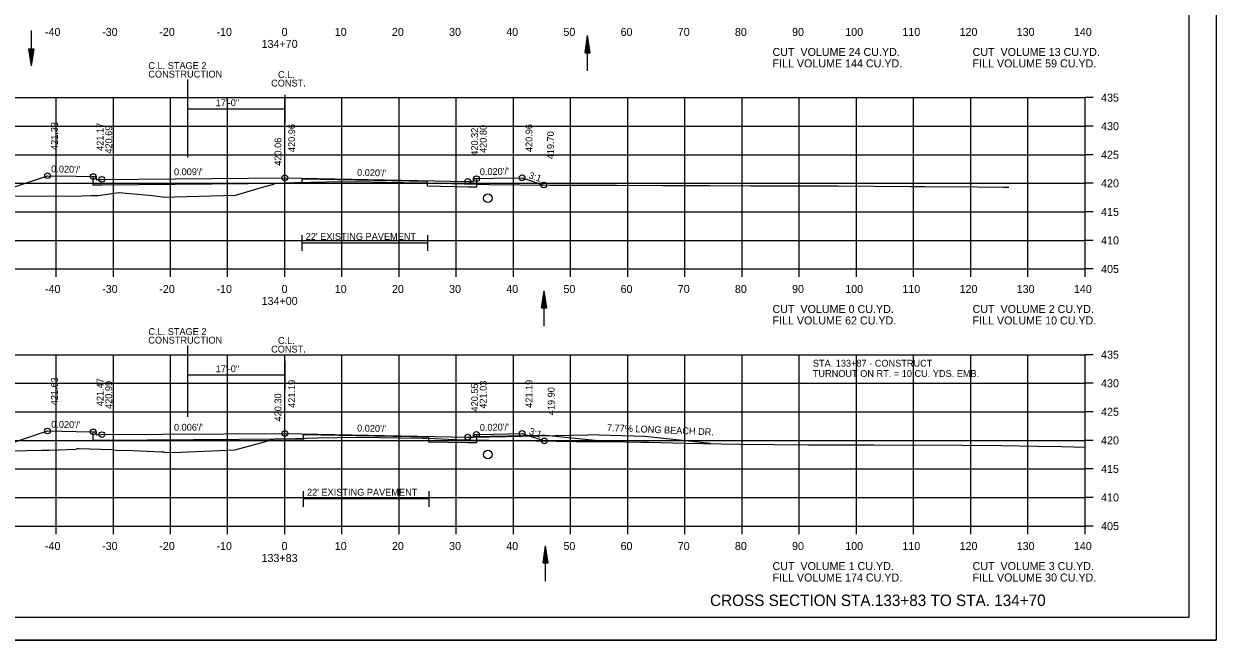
# Model space of a CAD drawing. Extents: x 1538688 to 1540766, y 656250 to 671912.
# Drawn here: x 1538812.5 to 1539021.1, y 661244.7 to 661352.6 of the extents above; entities that cross this region are included whole.
import ezdxf

# ---------------------------------------------------------------- set-up
doc = ezdxf.new("R2010")
doc.units = 0
for name, color, linetype in [('15', 7, 'Continuous'), ('16', 7, 'Continuous'), ('18', 7, 'Continuous'), ('20', 7, 'Continuous'), ('22', 7, 'Continuous'), ('26', 7, 'Continuous'), ('39', 7, 'Continuous'), ('41', 7, 'Continuous'), ('42', 7, 'Continuous'), ('7', 7, 'Continuous'), ('Borings', 7, 'Continuous'), ('Default', 7, 'Continuous'), ('Horizontal Alignment', 7, 'Continuous'), ('RipRap', 7, 'Continuous'), ('Wall Heights', 7, 'Continuous')]:
    doc.layers.add(name, color=color, linetype=linetype)

msp = doc.modelspace()

# ---------------------------------------------------------------- linework, layer by layer
at = {"layer": '15'}
for p, q in [((1538910.71, 661347.5), (1538911.16, 661350.5)), ((1538910.79, 661347.5), (1538911.16, 661349.99)), ((1538910.86, 661347.5), (1538911.16, 661349.48)), ((1538911.61, 661347.5), (1538911.16, 661350.5)), ((1538911.54, 661347.5), (1538911.16, 661349.99)), ((1538911.46, 661347.5), (1538911.16, 661349.48)), ((1538813.36, 661348.2), (1538813.81, 661345.2)), ((1538813.36, 661348.2), (1538814.26, 661348.2)), ((1538813.44, 661348.2), (1538813.81, 661345.7)), ((1538813.51, 661348.2), (1538813.81, 661346.22)), ((1538813.59, 661348.2), (1538813.81, 661346.72)), ((1538813.66, 661348.2), (1538813.81, 661347.23)), ((1538813.74, 661348.2), (1538813.81, 661347.73)), ((1538814.26, 661348.2), (1538813.81, 661345.2)), ((1538813.96, 661348.2), (1538813.81, 661347.23)), ((1538814.11, 661348.2), (1538813.81, 661346.22)), ((1538814.19, 661348.2), (1538813.81, 661345.7)), ((1538814.03, 661348.2), (1538813.81, 661346.72)), ((1538813.88, 661348.2), (1538813.81, 661347.73)), ((1538910.71, 661347.5), (1538911.61, 661347.5)), ((1538910.94, 661347.5), (1538911.16, 661348.98)), ((1538911.01, 661347.5), (1538911.16, 661348.47)), ((1538911.09, 661347.5), (1538911.16, 661347.97)), ((1538911.38, 661347.5), (1538911.16, 661348.98)), ((1538911.31, 661347.5), (1538911.16, 661348.47)), ((1538911.23, 661347.5), (1538911.16, 661347.97)), ((1538903.09, 661302.85), (1538903.54, 661305.85)), ((1538903.99, 661302.85), (1538903.54, 661305.85)), ((1538903.17, 661302.85), (1538903.54, 661305.34)), ((1538903.24, 661302.85), (1538903.54, 661304.83)), ((1538903.32, 661302.85), (1538903.54, 661304.33)), ((1538903.4, 661302.85), (1538903.54, 661303.82)), ((1538903.92, 661302.85), (1538903.54, 661305.34)), ((1538903.84, 661302.85), (1538903.54, 661304.83)), ((1538903.77, 661302.85), (1538903.54, 661304.33)), ((1538903.69, 661302.85), (1538903.54, 661303.82)), ((1538903.09, 661302.85), (1538903.99, 661302.85)), ((1538903.47, 661302.85), (1538903.54, 661303.32)), ((1538903.61, 661302.85), (1538903.54, 661303.32)), ((1538903.36, 661258.19), (1538903.81, 661261.19)), ((1538903.44, 661258.19), (1538903.81, 661260.69)), ((1538903.51, 661258.19), (1538903.81, 661260.18)), ((1538903.59, 661258.19), (1538903.81, 661259.68)), ((1538904.26, 661258.19), (1538903.81, 661261.19)), ((1538904.19, 661258.19), (1538903.81, 661260.69)), ((1538904.11, 661258.19), (1538903.81, 661260.18)), ((1538904.03, 661258.19), (1538903.81, 661259.68)), ((1538903.36, 661258.19), (1538904.26, 661258.19)), ((1538903.67, 661258.19), (1538903.81, 661259.17)), ((1538903.74, 661258.19), (1538903.81, 661258.67)), ((1538903.96, 661258.19), (1538903.81, 661259.17)), ((1538903.88, 661258.19), (1538903.81, 661258.67))]:
    msp.add_line(p, q, dxfattribs=at)
at = {"layer": '16'}
for p, q in [((1538891.18, 661280.19), (1538911.17, 661280.59)), ((1538891.18, 661280.3), (1538903.18, 661280.54)), ((1538914.15, 661279.44), (1538903.18, 661280.54)), ((1538921.17, 661280.33), (1538911.17, 661280.59)), ((1538932.64, 661279.09), (1538921.17, 661280.33))]:
    msp.add_line(p, q, dxfattribs=at)
at = {"layer": '18'}
for points in [[(1538809.48, 661322.39), (1538822.68, 661322.43), (1538824.23, 661322.5), (1538824.62, 661322.5), (1538824.96, 661322.52), (1538825.5, 661322.5), (1538829.15, 661323.05), (1538834.99, 661322.5), (1538837.19, 661322.23), (1538838.95, 661322.26), (1538849.56, 661322.59), (1538854.69, 661324.1), (1538856.25, 661324.5), (1538856.32, 661324.53), (1538856.53, 661324.68), (1538858.29, 661324.72), (1538859.86, 661324.76), (1538865.42, 661324.88), (1538870.63, 661324.98), (1538875.93, 661324.86), (1538882.01, 661324.75), (1538882.96, 661324.74), (1538893.99, 661324.43), (1538904.52, 661324.35), (1538916.23, 661324.31), (1538924.16, 661324.25), (1538932.48, 661324.26), (1538939.67, 661324.22), (1538946.19, 661324.23), (1538954.91, 661324.18), (1538967.64, 661324.1), (1538970.06, 661324.08), (1538979.33, 661324.02), (1538983.91, 661323.98), (1538984.85, 661323.99)], [(1538807.8, 661277.78), (1538815.66, 661277.95), (1538815.73, 661277.95), (1538816.96, 661277.95), (1538821.68, 661278.11), (1538821.9, 661278.2), (1538822.13, 661278.22), (1538827.92, 661278.03), (1538829.02, 661277.88), (1538830.36, 661277.92), (1538836.61, 661277.64), (1538836.95, 661277.63), (1538837.29, 661277.5), (1538839.97, 661277.59), (1538849.46, 661277.98), (1538854.2, 661279.25), (1538856.41, 661279.89), (1538857.66, 661279.94), (1538860.03, 661280), (1538863.9, 661280.08), (1538870.75, 661280.23), (1538870.84, 661280.21), (1538874.86, 661280.14), (1538882.22, 661280.03), (1538883.28, 661280.02), (1538889.11, 661279.76), (1538889.79, 661279.74), (1538902.07, 661279.58), (1538909.16, 661279.45), (1538915.03, 661279.44), (1538920.47, 661279.34), (1538921.91, 661279.31), (1538928.16, 661279.17), (1538937.79, 661278.99), (1538949.82, 661278.87), (1538958.4, 661278.87), (1538961.21, 661278.84), (1538976.59, 661278.81), (1538983.55, 661278.75), (1538989.87, 661278.65), (1538994.09, 661278.55), (1538998.18, 661278.43)]]:
    msp.add_lwpolyline(points, dxfattribs=at)
at = {"layer": '20'}
for points in [[(1538805.94, 661322.4), (1538816.67, 661325.98), (1538821.67, 661325.88), (1538824.67, 661325.82), (1538825.17, 661325.82), (1538825.18, 661325.32), (1538826.18, 661325.34), (1538858.18, 661325.62), (1538890.18, 661324.98), (1538891.18, 661324.96), (1538891.19, 661325.46), (1538891.69, 661325.46), (1538894.69, 661325.52), (1538899.69, 661325.62), (1538903.47, 661324.35)], [(1538803.72, 661277.74), (1538804.88, 661277.36), (1538816.67, 661281.29), (1538821.67, 661281.19), (1538824.67, 661281.13), (1538825.17, 661281.13), (1538825.18, 661280.63), (1538826.18, 661280.65), (1538858.18, 661280.85), (1538890.18, 661280.21), (1538891.18, 661280.19), (1538891.19, 661280.69), (1538891.69, 661280.69), (1538894.69, 661280.75), (1538899.69, 661280.85), (1538903.58, 661279.55)]]:
    msp.add_lwpolyline(points, dxfattribs=at)
at = {"layer": '22'}
for p, q in [((1538718.18, 661339.65), (1538998.18, 661339.65)), ((1538818.18, 661309.65), (1538818.18, 661339.65)), ((1538828.18, 661309.65), (1538828.18, 661339.65)), ((1538838.18, 661309.65), (1538838.18, 661339.65)), ((1538848.18, 661309.65), (1538848.18, 661339.65)), ((1538858.18, 661309.65), (1538858.18, 661339.65)), ((1538868.18, 661309.65), (1538868.18, 661339.65)), ((1538878.18, 661309.65), (1538878.18, 661339.65)), ((1538888.18, 661309.65), (1538888.18, 661339.65)), ((1538898.18, 661309.65), (1538898.18, 661339.65)), ((1538908.18, 661309.65), (1538908.18, 661339.65)), ((1538918.18, 661309.65), (1538918.18, 661339.65)), ((1538928.18, 661309.65), (1538928.18, 661339.65)), ((1538938.18, 661309.65), (1538938.18, 661339.65)), ((1538948.18, 661309.65), (1538948.18, 661339.65)), ((1538958.18, 661309.65), (1538958.18, 661339.65)), ((1538968.18, 661309.65), (1538968.18, 661339.65)), ((1538978.18, 661309.65), (1538978.18, 661339.65)), ((1538988.18, 661309.65), (1538988.18, 661339.65)), ((1538998.18, 661309.65), (1538998.18, 661339.65)), ((1538718.18, 661334.65), (1538998.18, 661334.65)), ((1538718.18, 661329.65), (1538998.18, 661329.65)), ((1538718.18, 661324.65), (1538998.18, 661324.65)), ((1538718.18, 661319.65), (1538998.18, 661319.65)), ((1538718.18, 661314.65), (1538998.18, 661314.65)), ((1538718.18, 661309.65), (1538998.18, 661309.65)), ((1538718.18, 661294.65), (1538998.18, 661294.65)), ((1538818.18, 661264.65), (1538818.18, 661294.65)), ((1538828.18, 661264.65), (1538828.18, 661294.65)), ((1538838.18, 661264.65), (1538838.18, 661294.65)), ((1538848.18, 661264.65), (1538848.18, 661294.65)), ((1538858.18, 661264.65), (1538858.18, 661294.65)), ((1538868.18, 661264.65), (1538868.18, 661294.65)), ((1538878.18, 661264.65), (1538878.18, 661294.65)), ((1538888.18, 661264.65), (1538888.18, 661294.65)), ((1538898.18, 661264.65), (1538898.18, 661294.65)), ((1538908.18, 661264.65), (1538908.18, 661294.65)), ((1538918.18, 661264.65), (1538918.18, 661294.65)), ((1538928.18, 661264.65), (1538928.18, 661294.65)), ((1538938.18, 661264.65), (1538938.18, 661294.65)), ((1538948.18, 661264.65), (1538948.18, 661294.65)), ((1538958.18, 661264.65), (1538958.18, 661294.65)), ((1538968.18, 661264.65), (1538968.18, 661294.65)), ((1538978.18, 661264.65), (1538978.18, 661294.65)), ((1538988.18, 661264.65), (1538988.18, 661294.65)), ((1538998.18, 661264.65), (1538998.18, 661294.65)), ((1538718.18, 661289.65), (1538998.18, 661289.65)), ((1538718.18, 661284.65), (1538998.18, 661284.65)), ((1538718.18, 661279.65), (1538998.18, 661279.65)), ((1538718.18, 661274.65), (1538998.18, 661274.65)), ((1538718.18, 661269.65), (1538998.18, 661269.65)), ((1538718.18, 661264.65), (1538998.18, 661264.65))]:
    msp.add_line(p, q, dxfattribs=at)
at = {"layer": '26'}
msp.add_line((1538687.78, 661244.68), (1539021.11, 661244.68), dxfattribs=at)
msp.add_lwpolyline([(1538687.77, 661458.01), (1539021.11, 661458.01), (1539021.11, 661244.67), (1538687.77, 661244.67)], close=True, dxfattribs=at)
for centre in [(1538816.67, 661325.98), (1538824.67, 661325.82), (1538826.18, 661325.34), (1538858.18, 661325.62), (1538890.18, 661324.98), (1538891.69, 661325.46), (1538899.69, 661325.62), (1538903.47, 661324.35), (1538816.67, 661281.29), (1538824.67, 661281.13), (1538826.18, 661280.65), (1538858.18, 661280.85), (1538890.18, 661280.21), (1538891.69, 661280.69), (1538899.69, 661280.85), (1538903.58, 661279.55)]:
    msp.add_circle(centre, 0.5, dxfattribs=at)
at = {"layer": '39'}
for p, q in [((1538813.81, 661351.39), (1538813.81, 661345.2)), ((1538911.16, 661344.31), (1538911.16, 661350.5)), ((1538903.54, 661299.66), (1538903.54, 661305.85)), ((1538903.81, 661255.01), (1538903.81, 661261.19))]:
    msp.add_line(p, q, dxfattribs=at)
for centre in [(1538893.68, 661322.03), (1538893.68, 661277.18)]:
    msp.add_circle(centre, 0.75, dxfattribs=at)
at = {"layer": '7'}
for p, q in [((1538861.13, 661315.56), (1538861.13, 661312.81)), ((1538883.13, 661314.18), (1538861.13, 661314.18)), ((1538883.13, 661315.56), (1538883.13, 661312.81)), ((1538861.36, 661270.78), (1538861.36, 661268.04)), ((1538883.36, 661270.78), (1538883.36, 661268.04)), ((1538883.36, 661269.41), (1538861.36, 661269.41))]:
    msp.add_line(p, q, dxfattribs=at)
at = {"layer": 'Borings'}
for p, q in [((1538998.18, 661309.65), (1538998.18, 661339.65)), ((1538999.58, 661339.65), (1538998.18, 661339.65)), ((1538999.58, 661334.65), (1538998.18, 661334.65)), ((1538999.58, 661329.65), (1538998.18, 661329.65)), ((1538999.58, 661324.65), (1538998.18, 661324.65)), ((1538999.58, 661319.65), (1538998.18, 661319.65)), ((1538999.58, 661314.65), (1538998.18, 661314.65)), ((1538718.18, 661309.65), (1538998.18, 661309.65)), ((1538818.18, 661308.25), (1538818.18, 661309.65)), ((1538828.18, 661308.25), (1538828.18, 661309.65)), ((1538838.18, 661308.25), (1538838.18, 661309.65)), ((1538848.18, 661308.25), (1538848.18, 661309.65)), ((1538858.18, 661308.25), (1538858.18, 661309.65)), ((1538868.18, 661308.25), (1538868.18, 661309.65)), ((1538878.18, 661308.25), (1538878.18, 661309.65)), ((1538888.18, 661308.25), (1538888.18, 661309.65)), ((1538898.18, 661308.25), (1538898.18, 661309.65)), ((1538908.18, 661308.25), (1538908.18, 661309.65)), ((1538918.18, 661308.25), (1538918.18, 661309.65)), ((1538928.18, 661308.25), (1538928.18, 661309.65)), ((1538938.18, 661308.25), (1538938.18, 661309.65)), ((1538948.18, 661308.25), (1538948.18, 661309.65)), ((1538958.18, 661308.25), (1538958.18, 661309.65)), ((1538968.18, 661308.25), (1538968.18, 661309.65)), ((1538978.18, 661308.25), (1538978.18, 661309.65)), ((1538988.18, 661308.25), (1538988.18, 661309.65)), ((1538998.18, 661308.25), (1538998.18, 661309.65)), ((1538999.58, 661309.65), (1538998.18, 661309.65)), ((1538998.18, 661264.65), (1538998.18, 661294.65)), ((1538999.58, 661294.65), (1538998.18, 661294.65)), ((1538999.58, 661289.65), (1538998.18, 661289.65)), ((1538999.58, 661284.65), (1538998.18, 661284.65)), ((1538999.58, 661279.65), (1538998.18, 661279.65)), ((1538999.58, 661274.65), (1538998.18, 661274.65)), ((1538999.58, 661269.65), (1538998.18, 661269.65)), ((1538718.18, 661264.65), (1538998.18, 661264.65)), ((1538818.18, 661263.25), (1538818.18, 661264.65)), ((1538828.18, 661263.25), (1538828.18, 661264.65)), ((1538838.18, 661263.25), (1538838.18, 661264.65)), ((1538848.18, 661263.25), (1538848.18, 661264.65)), ((1538858.18, 661263.25), (1538858.18, 661264.65)), ((1538868.18, 661263.25), (1538868.18, 661264.65)), ((1538878.18, 661263.25), (1538878.18, 661264.65)), ((1538888.18, 661263.25), (1538888.18, 661264.65)), ((1538898.18, 661263.25), (1538898.18, 661264.65)), ((1538908.18, 661263.25), (1538908.18, 661264.65)), ((1538918.18, 661263.25), (1538918.18, 661264.65)), ((1538928.18, 661263.25), (1538928.18, 661264.65)), ((1538938.18, 661263.25), (1538938.18, 661264.65)), ((1538948.18, 661263.25), (1538948.18, 661264.65)), ((1538958.18, 661263.25), (1538958.18, 661264.65)), ((1538968.18, 661263.25), (1538968.18, 661264.65)), ((1538978.18, 661263.25), (1538978.18, 661264.65)), ((1538988.18, 661263.25), (1538988.18, 661264.65)), ((1538998.18, 661263.25), (1538998.18, 661264.65)), ((1538999.58, 661264.65), (1538998.18, 661264.65))]:
    msp.add_line(p, q, dxfattribs=at)
at = {"layer": 'Default'}
for p, q in [((1538841.17, 661342.82), (1538841.17, 661329.18)), ((1538858.18, 661340.14), (1538858.18, 661335.14)), ((1538858.18, 661337.64), (1538841.17, 661337.64)), ((1538841.17, 661296.25), (1538841.17, 661283.78)), ((1538858.18, 661293.57), (1538858.18, 661288.57)), ((1538858.18, 661291.07), (1538841.17, 661291.07))]:
    msp.add_line(p, q, dxfattribs=at)
at = {"layer": 'RipRap'}
for q in [(1539016.36, 661454.11), (1538700.18, 661248.65)]:
    msp.add_line((1539016.36, 661248.65), q, dxfattribs=at)
at = {"layer": 'Wall Heights'}
for points in [[(1538891.69, 661325.46), (1538891.69, 661323.96), (1538890.18, 661323.98), (1538883.14, 661324.12), (1538883.14, 661324.95), (1538861.14, 661325.39), (1538861.14, 661324.56), (1538858.18, 661324.62), (1538826.18, 661324.34), (1538824.67, 661324.32), (1538824.67, 661325.82)], [(1538891.69, 661280.69), (1538891.69, 661279.19), (1538890.18, 661279.21), (1538883.37, 661279.34), (1538883.37, 661280.18), (1538861.37, 661280.62), (1538861.37, 661279.78), (1538858.18, 661279.85), (1538826.18, 661279.65), (1538824.67, 661279.63), (1538824.67, 661281.13)]]:
    msp.add_lwpolyline(points, dxfattribs=at)

# ---------------------------------------------------------------- texts
at = {"layer": '15'}
msp.add_text('CROSS SECTION STA.133+83 TO STA. 134+70', height=2, dxfattribs=at).set_placement((1538932.57, 661250.65))
at = {"layer": '16'}
msp.add_text('7.77% LONG BEACH DR.', height=1.2, rotation=357.6091, dxfattribs=at).set_placement((1538914.51, 661281.29))
at = {"layer": '41'}
for s, p in [('421.33', (1538818.47, 661330.48)), ('421.17', (1538826.47, 661330.32)), ('420.69', (1538827.98, 661329.84)), ('420.96', (1538859.98, 661330.12)), ('420.80', (1538893.49, 661329.96)), ('420.96', (1538901.49, 661330.12)), ('420.32', (1538891.98, 661329.48)), ('419.70', (1538905.27, 661328.85)), ('420.06', (1538857.58, 661327.72)), ('421.63', (1538818.47, 661285.79)), ('421.47', (1538826.47, 661285.63)), ('420.99', (1538827.98, 661285.15)), ('421.19', (1538859.98, 661285.35)), ('420.55', (1538891.98, 661284.71)), ('421.03', (1538893.49, 661285.19)), ('421.19', (1538901.49, 661285.35)), ('419.90', (1538905.38, 661284.05)), ('420.30', (1538857.58, 661282.96))]:
    msp.add_text(s, height=1.2, rotation=90, dxfattribs=at).set_placement(p)
at = {"layer": '42'}
for s, rotation, p in [("0.020'/'", 358.8542, (1538817.3, 661326.57)), ("0.009'/'", 0.4932, (1538838.79, 661326.05)), ("0.020'/'", 358.8542, (1538870.81, 661325.96)), ("0.020'/'", 1.1458, (1538892.3, 661326.07)), ('3:1', 341.5651, (1538900.74, 661325.56)), ("0.020'/'", 358.8542, (1538817.3, 661281.88)), ("0.006'/'", 0.3561, (1538838.79, 661281.33)), ("0.020'/'", 1.1458, (1538892.3, 661281.3)), ("0.020'/'", 358.8542, (1538870.81, 661281.2)), ('3:1', 341.5651, (1538900.79, 661280.77))]:
    msp.add_text(s, height=1.2, rotation=rotation, dxfattribs=at).set_placement(p)
at = {"layer": '7'}
for s, p in [("22' EXISTING PAVEMENT", (1538861.83, 661314.74)), ('STA. 133+87 - CONSTRUCT', (1538950.55, 661292.55)), ('TURNOUT ON RT. = 10 CU. YDS. EMB.', (1538950.55, 661290.75)), ("22' EXISTING PAVEMENT", (1538862.06, 661269.97))]:
    msp.add_text(s, height=1.2, dxfattribs=at).set_placement(p)
at = {"layer": 'Default'}
for s, p in [('C.L. STAGE 2', (1538834.31, 661344.66)), ('CONSTRUCTION', (1538834.3, 661343.16)), ('C.L.', (1538856.98, 661343.09)), ('CONST.', (1538855.78, 661341.59)), ('17\'-0"', (1538846.09, 661338.15)), ('C.L. STAGE 2', (1538834.31, 661298.09)), ('CONSTRUCTION', (1538834.3, 661296.59)), ('C.L.', (1538856.98, 661296.52)), ('CONST.', (1538855.78, 661295.02)), ('17\'-0"', (1538846.09, 661291.58))]:
    msp.add_text(s, height=1.2, dxfattribs=at).set_placement(p)
at = {"layer": 'Horizontal Alignment'}
for s, p in [('-40', (1538816.22, 661350.45)), ('-30', (1538826.22, 661350.45)), ('-20', (1538836.22, 661350.45)), ('-10', (1538846.22, 661350.45)), ('0', (1538857.62, 661350.45)), ('10', (1538866.92, 661350.45)), ('20', (1538876.92, 661350.45)), ('30', (1538886.92, 661350.45)), ('40', (1538896.92, 661350.45)), ('50', (1538906.92, 661350.45)), ('60', (1538916.92, 661350.45)), ('70', (1538926.92, 661350.45)), ('80', (1538936.92, 661350.45)), ('90', (1538946.92, 661350.45)), ('100', (1538956.22, 661350.45)), ('110', (1538966.22, 661350.45)), ('120', (1538976.22, 661350.45)), ('130', (1538986.22, 661350.45)), ('140', (1538996.22, 661350.45)), ('134+70', (1538854.12, 661348.35)), ('CUT  VOLUME 24 CU.YD.', (1538943.5, 661346.94)), ('CUT  VOLUME 13 CU.YD.', (1538978.5, 661346.94)), ('FILL VOLUME 144 CU.YD.', (1538943.5, 661344.94)), ('FILL VOLUME 59 CU.YD.', (1538978.5, 661344.94)), ('435', (1539000.98, 661338.95)), ('430', (1539000.98, 661333.95)), ('425', (1539000.98, 661328.95)), ('420', (1539000.98, 661323.95)), ('415', (1539000.98, 661318.95)), ('410', (1539000.98, 661313.95)), ('405', (1539000.98, 661308.95)), ('-40', (1538816.22, 661305.45)), ('-30', (1538826.22, 661305.45)), ('-20', (1538836.22, 661305.45)), ('-10', (1538846.22, 661305.45)), ('0', (1538857.62, 661305.45)), ('10', (1538866.92, 661305.45)), ('20', (1538876.92, 661305.45)), ('30', (1538886.92, 661305.45)), ('40', (1538896.92, 661305.45)), ('50', (1538906.92, 661305.45)), ('60', (1538916.92, 661305.45)), ('70', (1538926.92, 661305.45)), ('80', (1538936.92, 661305.45)), ('90', (1538946.92, 661305.45)), ('100', (1538956.22, 661305.45)), ('110', (1538966.22, 661305.45)), ('120', (1538976.22, 661305.45)), ('130', (1538986.22, 661305.45)), ('140', (1538996.22, 661305.45)), ('134+00', (1538854.12, 661303.35)), ('CUT  VOLUME 0 CU.YD.', (1538943.5, 661301.94)), ('FILL VOLUME 62 CU.YD.', (1538943.5, 661299.94)), ('CUT  VOLUME 2 CU.YD.', (1538978.5, 661301.94)), ('FILL VOLUME 10 CU.YD.', (1538978.5, 661299.94)), ('435', (1539000.98, 661293.95)), ('430', (1539000.98, 661288.95)), ('425', (1539000.98, 661283.95)), ('420', (1539000.98, 661278.95)), ('415', (1539000.98, 661273.95)), ('410', (1539000.98, 661268.95)), ('405', (1539000.98, 661263.95)), ('-40', (1538816.22, 661260.45)), ('-30', (1538826.22, 661260.45)), ('-20', (1538836.22, 661260.45)), ('-10', (1538846.22, 661260.45)), ('0', (1538857.62, 661260.45)), ('10', (1538866.92, 661260.45)), ('20', (1538876.92, 661260.45)), ('30', (1538886.92, 661260.45)), ('40', (1538896.92, 661260.45)), ('50', (1538906.92, 661260.45)), ('60', (1538916.92, 661260.45)), ('70', (1538926.92, 661260.45)), ('80', (1538936.92, 661260.45)), ('90', (1538946.92, 661260.45)), ('100', (1538956.22, 661260.45)), ('110', (1538966.22, 661260.45)), ('120', (1538976.22, 661260.45)), ('130', (1538986.22, 661260.45)), ('140', (1538996.22, 661260.45)), ('133+83', (1538854.11, 661258.35)), ('CUT  VOLUME 1 CU.YD.', (1538943.5, 661256.94)), ('CUT  VOLUME 3 CU.YD.', (1538978.5, 661256.94)), ('FILL VOLUME 174 CU.YD.', (1538943.5, 661254.94)), ('FILL VOLUME 30 CU.YD.', (1538978.5, 661254.94))]:
    msp.add_text(s, height=1.4, dxfattribs=at).set_placement(p)

doc.saveas('drawing.dxf')
